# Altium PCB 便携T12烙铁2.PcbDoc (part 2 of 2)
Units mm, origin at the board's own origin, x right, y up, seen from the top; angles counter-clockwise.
Board outline 100 x 95 mm, 2 copper layers (Top Layer, Bottom Layer); 155 components, 22 nets, 605 pads, 185 vias.
Unrouted connection lines stored in the file: 84.
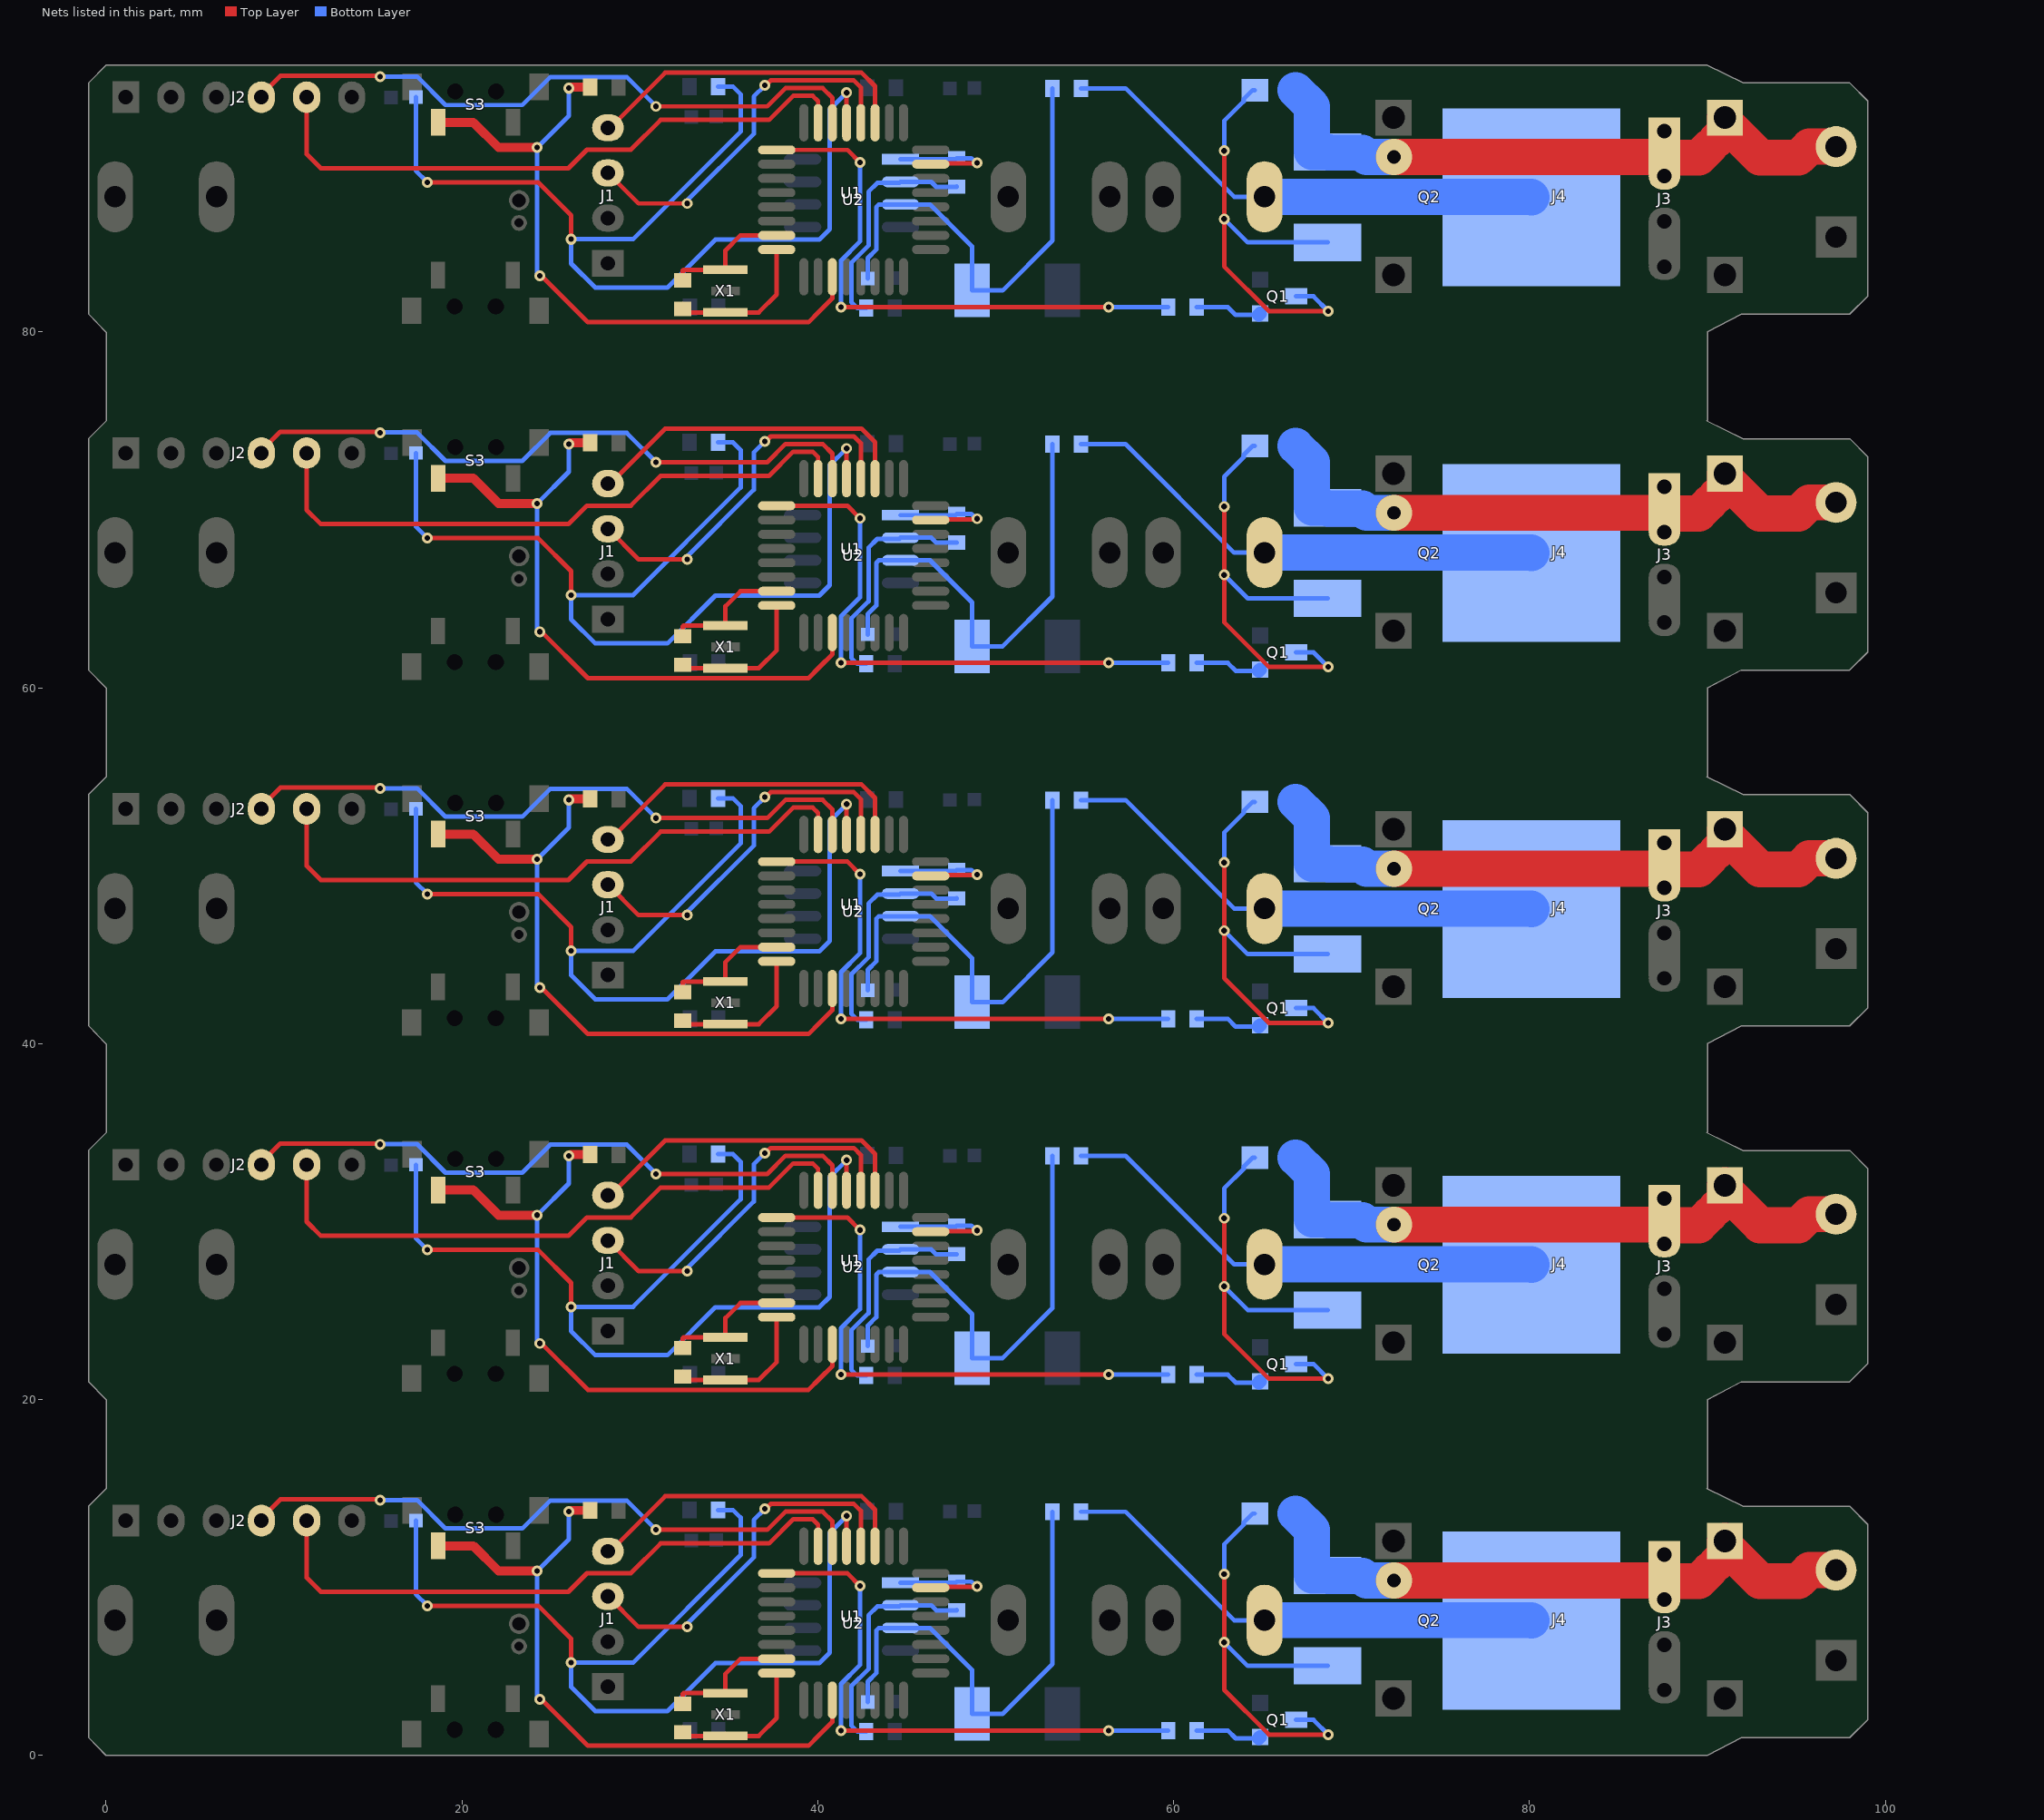
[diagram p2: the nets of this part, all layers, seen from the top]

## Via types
v1: diameter 0.61, hole 0.31, Top Layer to Bottom Layer, 120 vias
v2: diameter 0.62, hole 0.305, Top Layer to Bottom Layer, 30 vias
v3: diameter 0.61, hole 0.33, Top Layer to Bottom Layer, 20 vias
v4: diameter 0.61/0.61 (per signal layer), hole 0.33, Top Layer to Bottom Layer, 10 vias
v5: diameter 2.032/0.61 (per signal layer), hole 0.762, Top Layer to Bottom Layer, 5 vias

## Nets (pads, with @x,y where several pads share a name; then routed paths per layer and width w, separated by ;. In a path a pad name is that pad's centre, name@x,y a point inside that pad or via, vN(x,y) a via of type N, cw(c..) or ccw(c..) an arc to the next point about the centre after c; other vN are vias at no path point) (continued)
NetQ1_B: Q1.B R2.1 | length 18.9
  Bottom Layer w0.254: R2.1@61.297,1.401 63.049,1.401 63.493,0.958 Q1.B@64.785,0.958 ; R2.1@61.297,21.401 63.049,21.401 63.493,20.958 Q1.B@64.785,20.958 ; R2.1@61.297,41.401 63.049,41.401 63.493,40.958 Q1.B@64.785,40.958 ; R2.1@61.297,61.401 63.049,61.401 63.493,60.958 Q1.B@64.785,60.958 ; R2.1@61.297,81.401 63.049,81.401 63.493,80.958 Q1.B@64.785,80.958
  Bottom Layer w0.762: Q1.B@64.785,0.958 Q1.B@64.861,1.034 ; Q1.B@64.785,20.958 Q1.B@64.861,21.034 ; Q1.B@64.785,40.958 Q1.B@64.861,41.034 ; Q1.B@64.785,60.958 Q1.B@64.861,61.034 ; Q1.B@64.785,80.958 Q1.B@64.861,81.034
NetQ1_C: Q1.C Q2.G R3.1 | length 130.5
  Top Layer w0.254: v4(62.846,10.189) v4(62.846,6.354) 62.846,3.687 65.364,1.17 v1(68.696,1.17) ; v4(62.846,30.189) v4(62.846,26.354) 62.846,23.687 65.364,21.17 v1(68.696,21.17) ; v4(62.846,50.189) v4(62.846,46.354) 62.846,43.687 65.364,41.17 v1(68.696,41.17) ; v4(62.846,70.189) v4(62.846,66.354) 62.846,63.687 65.364,61.17 v1(68.696,61.17) ; v4(62.846,90.189) v4(62.846,86.354) 62.846,83.687 65.364,81.17 v1(68.696,81.17)
  Bottom Layer w0.254: v4(62.846,6.354) 64.167,5.033 Q2.G@68.663,5.033 ; v4(62.846,10.189) 62.846,11.866 63.938,12.958 63.938,13.085 64.446,13.593 R3.1@64.573,13.593 ; v4(62.846,26.354) 64.167,25.033 Q2.G@68.663,25.033 ; v4(62.846,30.189) 62.846,31.866 63.938,32.958 63.938,33.085 64.446,33.593 R3.1@64.573,33.593 ; v4(62.846,46.354) 64.167,45.033 Q2.G@68.663,45.033 ; v4(62.846,50.189) 62.846,51.866 63.938,52.958 63.938,53.085 64.446,53.593 R3.1@64.573,53.593 ; v4(62.846,66.354) 64.167,65.033 Q2.G@68.663,65.033 ; v4(62.846,70.189) 62.846,71.866 63.938,72.958 63.938,73.085 64.446,73.593 R3.1@64.573,73.593 ; v4(62.846,86.354) 64.167,85.033 Q2.G@68.663,85.033 ; v4(62.846,90.189) 62.846,91.866 63.938,92.958 63.938,93.085 64.446,93.593 R3.1@64.573,93.593 ; Q1.C@66.893,1.999 67.866,1.999 v1(68.696,1.17) ; Q1.C@66.893,21.999 67.866,21.999 v1(68.696,21.17) ; Q1.C@66.893,41.999 67.866,41.999 v1(68.696,41.17) ; Q1.C@66.893,61.999 67.866,61.999 v1(68.696,61.17) ; Q1.C@66.893,81.999 67.866,81.999 v1(68.696,81.17)
NetR10_1: R10.1 U2.8 X1.3 | length 41.5
  Top Layer w0.254: R10.1@32.415,1.298 32.614,1.1 X1.3@34.816,1.1 36.688,1.1 37.696,2.108 U2.8@37.696,4.631 ; R10.1@32.415,21.298 32.614,21.1 X1.3@34.816,21.1 36.688,21.1 37.696,22.108 U2.8@37.696,24.631 ; R10.1@32.415,41.298 32.614,41.1 X1.3@34.816,41.1 36.688,41.1 37.696,42.108 U2.8@37.696,44.631 ; R10.1@32.415,61.298 32.614,61.1 X1.3@34.816,61.1 36.688,61.1 37.696,62.108 U2.8@37.696,64.631 ; R10.1@32.415,81.298 32.614,81.1 X1.3@34.816,81.1 36.688,81.1 37.696,82.108 U2.8@37.696,84.631
NetR10_2: R10.2 U2.7 X1.1 | length 36.5
  Top Layer w0.254: R10.2@32.415,2.898 32.417,2.9 32.417,3.458 32.456,3.498 X1.1@34.816,3.498 34.816,4.587 35.659,5.431 U2.7@37.696,5.431 ; R10.2@32.415,22.898 32.417,22.9 32.417,23.458 32.456,23.498 X1.1@34.816,23.498 34.816,24.587 35.659,25.431 U2.7@37.696,25.431 ; R10.2@32.415,42.898 32.417,42.9 32.417,43.458 32.456,43.498 X1.1@34.816,43.498 34.816,44.587 35.659,45.431 U2.7@37.696,45.431 ; R10.2@32.415,62.898 32.417,62.9 32.417,63.458 32.456,63.498 X1.1@34.816,63.498 34.816,64.587 35.659,65.431 U2.7@37.696,65.431 ; R10.2@32.415,82.898 32.417,82.9 32.417,83.458 32.456,83.498 X1.1@34.816,83.498 34.816,84.587 35.659,85.431 U2.7@37.696,85.431
PWM_MOS: R2.2 U2.1 | length 159.6
  Top Layer w0.254: U2.1@37.696,10.231 41.672,10.231 v1(42.374,9.529) ; U2.1@37.696,30.231 41.672,30.231 v1(42.374,29.529) ; U2.1@37.696,50.231 41.672,50.231 v1(42.374,49.529) ; U2.1@37.696,70.231 41.672,70.231 v1(42.374,69.529) ; U2.1@37.696,90.231 41.672,90.231 v1(42.374,89.529) ; v1(41.307,1.401) v1(56.344,1.401) ; v1(41.307,21.401) v1(56.344,21.401) ; v1(41.307,41.401) v1(56.344,41.401) ; v1(41.307,61.401) v1(56.344,61.401) ; v1(41.307,81.401) v1(56.344,81.401)
  Bottom Layer w0.254: v1(41.307,1.401) 41.307,4.017 42.374,5.084 v1(42.374,9.529) ; v1(41.307,21.401) 41.307,24.017 42.374,25.084 v1(42.374,29.529) ; v1(41.307,41.401) 41.307,44.017 42.374,45.084 v1(42.374,49.529) ; v1(41.307,61.401) 41.307,64.017 42.374,65.084 v1(42.374,69.529) ; v1(41.307,81.401) 41.307,84.017 42.374,85.084 v1(42.374,89.529) ; v1(56.344,1.401) R2.2@59.697,1.401 ; v1(56.344,21.401) R2.2@59.697,21.401 ; v1(56.344,41.401) R2.2@59.697,41.401 ; v1(56.344,61.401) R2.2@59.697,61.401 ; v1(56.344,81.401) R2.2@59.697,81.401
R_but: R8.2 S3.2 U2.11 | length 190
  Top Layer w0.254: v1(24.391,3.154) 24.477,3.154 27.085,0.546 39.482,0.546 40.112,1.176 40.823,1.887 U2.11@40.823,3.104 ; v1(24.391,23.154) 24.477,23.154 27.085,20.546 39.482,20.546 40.112,21.176 40.823,21.887 U2.11@40.823,23.104 ; v1(24.391,43.154) 24.477,43.154 27.085,40.546 39.482,40.546 40.112,41.176 40.823,41.887 U2.11@40.823,43.104 ; v1(24.391,63.154) 24.477,63.154 27.085,60.546 39.482,60.546 40.112,61.176 40.823,61.887 U2.11@40.823,63.104 ; v1(24.391,83.154) 24.477,83.154 27.085,80.546 39.482,80.546 40.112,81.176 40.823,81.887 U2.11@40.823,83.104
  Top Layer w0.508: S3.2@18.674,11.779 20.643,11.779 22.054,10.367 v1(24.238,10.367) ; S3.2@18.674,31.779 20.643,31.779 22.054,30.367 v1(24.238,30.367) ; S3.2@18.674,51.779 20.643,51.779 22.054,50.367 v1(24.238,50.367) ; S3.2@18.674,71.779 20.643,71.779 22.054,70.367 v1(24.238,70.367) ; S3.2@18.674,91.779 20.643,91.779 22.054,90.367 v1(24.238,90.367) ; v2(26.016,13.699) 26.046,13.699 26.118,13.771 R8.2@27.21,13.771 ; v2(26.016,33.699) 26.046,33.699 26.118,33.771 R8.2@27.21,33.771 ; v2(26.016,53.699) 26.046,53.699 26.118,53.771 R8.2@27.21,53.771 ; v2(26.016,73.699) 26.046,73.699 26.118,73.771 R8.2@27.21,73.771 ; v2(26.016,93.699) 26.046,93.699 26.118,93.771 R8.2@27.21,93.771
  Bottom Layer w0.254: v1(24.391,3.154) 24.238,3.306 v1(24.238,10.367) 26.016,12.145 v2(26.016,13.699) ; v1(24.391,23.154) 24.238,23.306 v1(24.238,30.367) 26.016,32.145 v2(26.016,33.699) ; v1(24.391,43.154) 24.238,43.306 v1(24.238,50.367) 26.016,52.145 v2(26.016,53.699) ; v1(24.391,63.154) 24.238,63.306 v1(24.238,70.367) 26.016,72.145 v2(26.016,73.699) ; v1(24.391,83.154) 24.238,83.306 v1(24.238,90.367) 26.016,92.145 v2(26.016,93.699)
Reset: C2.2 R9.1 U2.29 | length 292.4
  Top Layer w0.254: v2(18.066,8.411) 24.289,8.411 26.143,6.557 v2(26.143,5.211) ; v2(18.066,28.411) 24.289,28.411 26.143,26.557 v2(26.143,25.211) ; v2(18.066,48.411) 24.289,48.411 26.143,46.557 v2(26.143,45.211) ; v2(18.066,68.411) 24.289,68.411 26.143,66.557 v2(26.143,65.211) ; v2(18.066,88.411) 24.289,88.411 26.143,86.557 v2(26.143,85.211) ; U2.29@41.576,11.805 U2.29@41.623,11.758 v3(41.623,13.455) ; U2.29@41.576,31.805 U2.29@41.623,31.758 v3(41.623,33.455) ; U2.29@41.576,51.805 U2.29@41.623,51.758 v3(41.623,53.455) ; U2.29@41.576,71.805 U2.29@41.623,71.758 v3(41.623,73.455) ; U2.29@41.576,91.805 U2.29@41.623,91.758 v3(41.623,93.455)
  Bottom Layer w0.254: C2.2@17.414,13.199 17.414,9.063 v2(18.066,8.411) ; C2.2@17.414,33.199 17.414,29.063 v2(18.066,28.411) ; C2.2@17.414,53.199 17.414,49.063 v2(18.066,48.411) ; C2.2@17.414,73.199 17.414,69.063 v2(18.066,68.411) ; C2.2@17.414,93.199 17.414,89.063 v2(18.066,88.411) ; R9.1@34.398,13.796 35.236,13.796 35.668,13.365 35.668,11.256 29.623,5.211 v2(26.143,5.211) 26.143,3.847 27.497,2.493 31.553,2.493 34.246,5.186 40.088,5.186 40.672,5.77 40.672,12.505 v3(41.623,13.455) ; R9.1@34.398,33.796 35.236,33.796 35.668,33.365 35.668,31.256 29.623,25.211 v2(26.143,25.211) 26.143,23.847 27.497,22.493 31.553,22.493 34.246,25.186 40.088,25.186 40.672,25.77 40.672,32.505 v3(41.623,33.455) ; R9.1@34.398,53.796 35.236,53.796 35.668,53.365 35.668,51.256 29.623,45.211 v2(26.143,45.211) 26.143,43.847 27.497,42.493 31.553,42.493 34.246,45.186 40.088,45.186 40.672,45.77 40.672,52.505 v3(41.623,53.455) ; R9.1@34.398,73.796 35.236,73.796 35.668,73.365 35.668,71.256 29.623,65.211 v2(26.143,65.211) 26.143,63.847 27.497,62.493 31.553,62.493 34.246,65.186 40.088,65.186 40.672,65.77 40.672,72.505 v3(41.623,73.455) ; R9.1@34.398,93.796 35.236,93.796 35.668,93.364 35.668,91.256 29.623,85.211 v2(26.143,85.211) 26.143,83.847 27.497,82.493 31.553,82.493 34.246,85.186 40.088,85.186 40.672,85.77 40.672,92.505 v3(41.623,93.455)
RX: J2.4 U2.30 | length 183.7
  Top Layer w0.254: J2.4@8.735,13.198 8.735,13.325 9.802,14.392 15.369,14.392 v1(15.416,14.345) ; J2.4@8.735,33.198 8.735,33.325 9.802,34.392 15.369,34.392 v1(15.416,34.345) ; J2.4@8.735,53.198 8.735,53.325 9.802,54.392 15.369,54.392 v1(15.416,54.345) ; J2.4@8.735,73.198 8.735,73.325 9.802,74.392 15.369,74.392 v1(15.416,74.345) ; J2.4@8.735,93.198 8.735,93.325 9.802,94.392 15.369,94.392 v1(15.416,94.345) ; v1(30.918,12.679) 37.167,12.679 38.191,13.703 40.282,13.703 40.823,13.163 U2.30@40.823,11.758 ; v1(30.918,32.679) 37.167,32.679 38.191,33.703 40.282,33.703 40.823,33.163 U2.30@40.823,31.758 ; v1(30.918,52.679) 37.167,52.679 38.191,53.703 40.282,53.703 40.823,53.163 U2.30@40.823,51.758 ; v1(30.918,72.679) 37.167,72.679 38.191,73.703 40.282,73.703 40.823,73.163 U2.30@40.823,71.758 ; v1(30.918,92.679) 37.167,92.679 38.191,93.703 40.282,93.703 40.823,93.163 U2.30@40.823,91.758
  Bottom Layer w0.254: v1(15.416,14.345) 15.426,14.355 17.482,14.355 19.082,12.755 23.4,12.755 24.975,14.33 29.267,14.33 v1(30.918,12.679) ; v1(15.416,34.345) 15.426,34.355 17.482,34.355 19.082,32.755 23.4,32.755 24.975,34.33 29.267,34.33 v1(30.918,32.679) ; v1(15.416,54.345) 15.426,54.355 17.482,54.355 19.082,52.755 23.4,52.755 24.975,54.33 29.267,54.33 v1(30.918,52.679) ; v1(15.416,74.345) 15.426,74.355 17.482,74.355 19.082,72.755 23.4,72.755 24.975,74.33 29.267,74.33 v1(30.918,72.679) ; v1(15.416,94.345) 15.426,94.355 17.482,94.355 19.082,92.755 23.4,92.755 24.975,94.33 29.267,94.33 v1(30.918,92.679)
SCL: J1.3 U2.28 | length 106.3
  Top Layer w0.254: J1.3@28.214,8.938 29.93,7.222 v1(32.671,7.222) ; J1.3@28.214,28.938 29.93,27.222 v1(32.671,27.222) ; J1.3@28.214,48.938 29.93,47.222 v1(32.671,47.222) ; J1.3@28.214,68.938 29.93,67.222 v1(32.671,67.222) ; J1.3@28.214,88.938 29.93,87.222 v1(32.671,87.222) ; v1(37.032,13.86) 37.083,13.86 37.359,14.135 42.035,14.135 42.423,13.747 U2.28@42.423,11.758 ; v1(37.032,33.86) 37.083,33.86 37.359,34.135 42.035,34.135 42.423,33.747 U2.28@42.423,31.758 ; v1(37.032,53.86) 37.083,53.86 37.359,54.135 42.035,54.135 42.423,53.747 U2.28@42.423,51.758 ; v1(37.032,73.86) 37.083,73.86 37.359,74.135 42.035,74.135 42.423,73.747 U2.28@42.423,71.758 ; v1(37.032,93.86) 37.083,93.86 37.359,94.135 42.035,94.135 42.423,93.747 U2.28@42.423,91.758
  Bottom Layer w0.254: v1(32.671,7.222) 32.671,7.394 36.405,11.128 36.405,13.232 v1(37.032,13.86) ; v1(32.671,27.222) 32.671,27.394 36.405,31.128 36.405,33.232 v1(37.032,33.86) ; v1(32.671,47.222) 32.671,47.394 36.405,51.128 36.405,53.232 v1(37.032,53.86) ; v1(32.671,67.222) 32.671,67.394 36.405,71.128 36.405,73.232 v1(37.032,73.86) ; v1(32.671,87.222) 32.671,87.394 36.405,91.128 36.405,93.232 v1(37.032,93.86)
SDA: J1.4 U2.27 | length 93.3
  Top Layer w0.254: J1.4@28.214,11.478 28.341,11.478 31.43,14.567 42.467,14.567 43.223,13.811 U2.27@43.223,11.758 ; J1.4@28.214,31.478 28.341,31.478 31.43,34.567 42.467,34.567 43.223,33.811 U2.27@43.223,31.758 ; J1.4@28.214,51.478 28.341,51.478 31.43,54.567 42.467,54.567 43.223,53.811 U2.27@43.223,51.758 ; J1.4@28.214,71.478 28.341,71.478 31.43,74.567 42.467,74.567 43.223,73.811 U2.27@43.223,71.758 ; J1.4@28.214,91.478 28.341,91.478 31.43,94.567 42.467,94.567 43.223,93.811 U2.27@43.223,91.758
TEMP: R5.1 U1.1 U2.23 | length 35.3
  Top Layer w0.254: U2.23@46.35,9.431 46.386,9.467 48.916,9.467 v1(48.952,9.503) ; U2.23@46.35,29.431 46.386,29.467 48.916,29.467 v1(48.952,29.503) ; U2.23@46.35,49.431 46.386,49.467 48.916,49.467 v1(48.952,49.503) ; U2.23@46.35,69.431 46.386,69.467 48.916,69.467 v1(48.952,69.503) ; U2.23@46.35,89.431 46.386,89.467 48.916,89.467 v1(48.952,89.503)
  Bottom Layer w0.254: U1.1@44.655,9.707 47.755,9.707 R5.1@47.817,9.769 48.639,9.769 48.904,9.503 v1(48.952,9.503) ; U1.1@44.655,29.707 47.755,29.707 R5.1@47.817,29.769 48.639,29.769 48.904,29.503 v1(48.952,29.503) ; U1.1@44.655,49.707 47.755,49.707 R5.1@47.817,49.769 48.639,49.769 48.904,49.503 v1(48.952,49.503) ; U1.1@44.655,69.707 47.755,69.707 R5.1@47.817,69.769 48.639,69.769 48.904,69.503 v1(48.952,69.503) ; U1.1@44.655,89.707 47.755,89.707 R5.1@47.817,89.769 48.639,89.769 48.904,89.503 v1(48.952,89.503)
TEMP_sense: P2.1 Q2.D R1.1 | length 139.3
  Bottom Layer w0.254: R1.1@54.794,13.695 57.307,13.695 63.403,7.599 P2.1@65.114,7.599 ; R1.1@54.794,33.695 57.307,33.695 63.403,27.599 P2.1@65.114,27.599 ; R1.1@54.794,53.695 57.307,53.695 63.403,47.599 P2.1@65.114,47.599 ; R1.1@54.794,73.695 57.307,73.695 63.403,67.599 P2.1@65.114,67.599 ; R1.1@54.794,93.695 57.307,93.695 63.403,87.599 P2.1@65.114,87.599
  Bottom Layer w2.032: P2.1@65.114,7.599 80.087,7.599 Q2.D@80.113,7.573 ; P2.1@65.114,27.599 80.087,27.599 Q2.D@80.113,27.573 ; P2.1@65.114,47.599 80.087,47.599 Q2.D@80.113,47.573 ; P2.1@65.114,67.599 80.087,67.599 Q2.D@80.113,67.573 ; P2.1@65.114,87.599 80.087,87.599 Q2.D@80.113,87.573
TX: J2.5 U2.31 | length 176.5
  Top Layer w0.254: J2.5@11.275,13.198 11.275,9.995 12.072,9.199 25.991,9.199 27.032,10.24 29.496,10.24 31.172,11.917 37.268,11.917 38.623,13.271 39.724,13.271 40.023,12.972 U2.31@40.023,11.758 ; J2.5@11.275,33.198 11.275,29.995 12.072,29.199 25.991,29.199 27.032,30.24 29.496,30.24 31.172,31.917 37.268,31.917 38.623,33.272 39.724,33.272 40.023,32.972 U2.31@40.023,31.758 ; J2.5@11.275,53.198 11.275,49.995 12.072,49.199 25.991,49.199 27.032,50.24 29.496,50.24 31.172,51.917 37.268,51.917 38.623,53.271 39.724,53.271 40.023,52.972 U2.31@40.023,51.758 ; J2.5@11.275,73.198 11.275,69.995 12.072,69.199 25.991,69.199 27.032,70.24 29.496,70.24 31.172,71.917 37.268,71.917 38.623,73.272 39.724,73.272 40.023,72.972 U2.31@40.023,71.758 ; J2.5@11.275,93.198 11.275,89.995 12.072,89.199 25.991,89.199 27.032,90.24 29.496,90.24 31.172,91.917 37.268,91.917 38.623,93.271 39.724,93.271 40.023,92.972 U2.31@40.023,91.758
V+: C1.2 R1.2 SS1.K U1.3 | length 136.8
  Bottom Layer w0.254: C1.2@42.813,3.001 42.813,4.15 43.288,4.625 43.288,7.018 43.437,7.167 U1.3@44.655,7.167 46.311,7.167 48.677,4.801 SS1.K@48.677,2.333 50.392,2.333 53.194,5.135 R1.2@53.194,13.695 ; C1.2@42.813,23.001 42.813,24.15 43.288,24.625 43.288,27.018 43.437,27.167 U1.3@44.655,27.167 46.311,27.167 48.677,24.801 SS1.K@48.677,22.333 50.392,22.333 53.194,25.135 R1.2@53.194,33.695 ; C1.2@42.813,43.001 42.813,44.15 43.288,44.625 43.288,47.018 43.437,47.167 U1.3@44.655,47.167 46.311,47.167 48.677,44.801 SS1.K@48.677,42.333 50.392,42.333 53.194,45.135 R1.2@53.194,53.695 ; C1.2@42.813,63.001 42.813,64.15 43.288,64.625 43.288,67.018 43.437,67.167 U1.3@44.655,67.167 46.311,67.167 48.677,64.801 SS1.K@48.677,62.333 50.392,62.333 53.194,65.135 R1.2@53.194,73.695 ; C1.2@42.813,83.001 42.813,84.15 43.288,84.625 43.288,87.018 43.437,87.167 U1.3@44.655,87.167 46.311,87.167 48.677,84.801 SS1.K@48.677,82.333 50.392,82.333 53.194,85.135 R1.2@53.194,93.695
V-: R4.1 R5.2 U1.2 | length 64.4
  Bottom Layer w0.254: R4.1@42.73,1.35 42.221,1.35 41.891,1.68 41.891,3.89 42.856,4.855 42.856,7.878 43.349,8.371 44.589,8.371 U1.2@44.655,8.437 46.387,8.437 46.666,8.157 47.806,8.157 R5.2@47.817,8.169 ; R4.1@42.73,21.35 42.221,21.35 41.891,21.68 41.891,23.89 42.856,24.855 42.856,27.878 43.349,28.371 44.589,28.371 U1.2@44.655,28.437 46.387,28.437 46.666,28.157 47.806,28.157 R5.2@47.817,28.169 ; R4.1@42.73,41.35 42.221,41.35 41.891,41.68 41.891,43.89 42.856,44.855 42.856,47.878 43.349,48.371 44.589,48.371 U1.2@44.655,48.437 46.387,48.437 46.666,48.157 47.806,48.157 R5.2@47.817,48.169 ; R4.1@42.73,61.35 42.221,61.35 41.891,61.68 41.891,63.89 42.856,64.855 42.856,67.878 43.349,68.371 44.589,68.371 U1.2@44.655,68.437 46.387,68.437 46.666,68.157 47.806,68.157 R5.2@47.817,68.169 ; R4.1@42.73,81.35 42.221,81.35 41.891,81.68 41.891,83.89 42.856,84.855 42.856,87.878 43.349,88.371 44.589,88.371 U1.2@44.655,88.437 46.387,88.437 46.666,88.157 47.806,88.157 R5.2@47.817,88.169
VCC: J3.1 J4.IN+ J5.2 Q2.S R3.2 | length 176.8
  Top Layer w2.032: v5(72.397,9.834) 87.554,9.834 J3.1@87.59,9.798 89.52,9.798 90.133,10.411 ; v5(72.397,29.834) 87.554,29.834 J3.1@87.59,29.798 89.52,29.798 90.133,30.411 ; v5(72.397,49.834) 87.554,49.834 J3.1@87.59,49.798 89.52,49.798 90.133,50.411 ; v5(72.397,69.834) 87.554,69.834 J3.1@87.59,69.798 89.52,69.798 90.133,70.411 ; v5(72.397,89.834) 87.554,89.834 J3.1@87.59,89.798 89.52,89.798 90.133,90.411 ; 90.514,10.792 90.989,11.268 J4.IN+@90.989,11.779 ; 90.514,30.792 90.989,31.268 J4.IN+@90.989,31.779 ; 90.514,50.792 90.989,51.268 J4.IN+@90.989,51.779 ; 90.514,70.792 90.989,71.268 J4.IN+@90.989,71.779 ; 90.514,90.792 90.989,91.268 J4.IN+@90.989,91.779 ; J4.IN+@90.989,12.044 J4.IN+@90.989,11.779 ; J4.IN+@90.989,32.044 J4.IN+@90.989,31.779 ; J4.IN+@90.989,52.044 J4.IN+@90.989,51.779 ; J4.IN+@90.989,72.044 J4.IN+@90.989,71.779 ; J4.IN+@90.989,92.044 J4.IN+@90.989,91.779 ; J5.2@97.238,10.418 95.739,10.418 95.119,9.798 92.971,9.798 J4.IN+@90.989,11.779 ; J5.2@97.238,30.418 95.739,30.418 95.119,29.798 92.971,29.798 J4.IN+@90.989,31.779 ; J5.2@97.238,50.418 95.739,50.418 95.119,49.798 92.971,49.798 J4.IN+@90.989,51.779 ; J5.2@97.238,70.418 95.739,70.418 95.119,69.798 92.971,69.798 J4.IN+@90.989,71.779 ; J5.2@97.238,90.418 95.739,90.418 95.119,89.798 92.971,89.798 J4.IN+@90.989,91.779
  Bottom Layer w2.032: R3.2@66.859,13.593 67.779,12.674 67.779,10.147 67.813,10.113 Q2.S@68.663,10.113 68.697,10.079 70.615,10.079 70.861,9.834 v5(72.397,9.834) ; R3.2@66.859,33.593 67.779,32.674 67.779,30.147 67.813,30.113 Q2.S@68.663,30.113 68.697,30.079 70.615,30.079 70.861,29.834 v5(72.397,29.834) ; R3.2@66.859,53.593 67.779,52.674 67.779,50.147 67.813,50.113 Q2.S@68.663,50.113 68.697,50.079 70.615,50.079 70.861,49.834 v5(72.397,49.834) ; R3.2@66.859,73.593 67.779,72.674 67.779,70.147 67.813,70.113 Q2.S@68.663,70.113 68.697,70.079 70.615,70.079 70.861,69.834 v5(72.397,69.834) ; R3.2@66.859,93.593 67.779,92.674 67.779,90.147 67.813,90.113 Q2.S@68.663,90.113 68.697,90.079 70.615,90.079 70.861,89.834 v5(72.397,89.834)
pads on no net: J2.2 P1.1 P1.2 P2.2 P3.2 S2.0 S3.0 U1.5 U1.6 U1.7 U2.9 U2.10 U2.12 U2.13 U2.14 U2.15 U2.16 U2.17 U2.19 U2.22 U2.25 U2.26 U2.32

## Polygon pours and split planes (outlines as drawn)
GND on Bottom Layer "GND_L02_P000" (solid, remove dead copper, pour order 0): -8.763,101.727 -4.953,97.917 103.124,97.917 103.124,0.254 98.933,-3.937 98.298,-3.302 -6.223,-3.302
GND on Top Layer "GND_L01_P001" (solid, remove dead copper, pour order 1): -12.7,106.299 106.299,106.299 109.601,102.997 104.648,98.044 104.648,-10.922 -2.921,-10.922 -12.446,-1.397

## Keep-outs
Keep-Out Layer:
  lines w0.254: 0,20 -0.986,21.008 -0.986,33.998 0.015,34.999 0.015,39.985 ; 0,40 -0.986,41.008 -0.986,53.998 0.015,54.999 0.015,59.985 ; 0,60 -0.986,61.008 -0.986,73.998 0.015,74.999 0.015,79.985 ; 0,80 -0.986,81.008 -0.986,93.998 0.015,94.999 89.98,94.999 92.014,93.998 98.008,93.998 99.014,92.984 99.014,82.012 98.003,80.998 91.915,80.998 90.013,80 90.013,75.032 ; 0.015,19.985 0.015,14.999 -0.986,13.998 -0.986,1.008 0,0 90.013,0 91.915,0.998 98.003,0.998 99.014,2.012 99.014,12.984 98.008,13.998 92.014,13.998 89.98,14.999 ; 5,14.999 5,19.999 54.75,19.999 ; 5,34.999 5,39.999 54.75,39.999 ; 5,54.999 5,59.999 54.75,59.999 ; 5,74.999 5,79.999 54.75,79.999 ; 5.015,14.999 54.765,14.999 54.765,19.999 ; 5.015,34.999 54.765,34.999 54.765,39.999 ; 5.015,54.999 54.765,54.999 54.765,59.999 ; 5.015,74.999 54.765,74.999 54.765,79.999 ; 89.98,34.999 92.014,33.998 98.008,33.998 99.014,32.984 99.014,22.012 98.003,20.998 91.915,20.998 90.013,20 90.013,15.032 ; 89.98,54.999 92.014,53.998 98.008,53.998 99.014,52.984 99.014,42.012 98.003,40.998 91.915,40.998 90.013,40 90.013,35.032 ; 89.98,74.999 92.014,73.998 98.008,73.998 99.014,72.984 99.014,62.012 98.003,60.998 91.915,60.998 90.013,60 90.013,55.032 ; 59.765,14.999 84.979,14.999 84.979,19.999 59.765,19.999 59.765,14.999 ; 59.765,34.999 59.765,39.999 84.979,39.999 84.979,34.999 59.765,34.999 ; 59.765,54.999 59.765,59.999 84.979,59.999 84.979,54.999 59.765,54.999 ; 59.765,74.999 59.765,79.999 84.979,79.999 84.979,74.999 59.765,74.999

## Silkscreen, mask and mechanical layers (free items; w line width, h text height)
Top Overlay:
  text "2K" at 29.775,93.212 h1.27
  text "24V" at 93.479,91.383 h2.54
  text "5V" at 67.85,91.231 h2.54
  text "GND" at 0.032,90.935 h1.27
  text "5V" at 5.569,90.94 h1.27
  text "RX" at 8.16,90.932 h1.27
  text "TX" at 10.649,90.932 h1.27
  text "DTR" at 12.808,90.932 h1.27
  text "SDA" at 29.748,90.819 h1.27
  text "SCL" at 29.648,88.149 h1.27
  text "T-" at 52.762,86.887 h2.54
  text "T+" at 60.992,86.735 h2.54
  text "5V" at 29.721,86.011 h1.27
  text "Vibrate" at 8.367,85.371 h1.27
  text "16M" at 33.357,84.982 h1.27
  text "GND" at 29.62,83.623 h1.27
  text "I2C" at 26.603,82.59 h1.27 r90
  text "GND" at 93.377,82.315 h2.54
  text "GND" at 65.589,82.29 h2.54
  text "1M" at 29.064,81.223 h1.27
  text "2K" at 29.775,73.212 h1.27
  text "24V" at 93.479,71.383 h2.54
  text "5V" at 67.85,71.231 h2.54
  text "GND" at 0.032,70.935 h1.27
  text "5V" at 5.569,70.94 h1.27
  text "RX" at 8.16,70.932 h1.27
  text "TX" at 10.649,70.932 h1.27
  text "DTR" at 12.808,70.932 h1.27
  text "SDA" at 29.748,70.819 h1.27
  text "SCL" at 29.648,68.149 h1.27
  text "T-" at 52.762,66.887 h2.54
  text "T+" at 60.992,66.735 h2.54
  text "5V" at 29.721,66.011 h1.27
  text "Vibrate" at 8.367,65.371 h1.27
  text "16M" at 33.357,64.982 h1.27
  text "GND" at 29.62,63.623 h1.27
  text "I2C" at 26.603,62.59 h1.27 r90
  text "GND" at 93.377,62.315 h2.54
  text "GND" at 65.589,62.29 h2.54
  text "1M" at 29.064,61.223 h1.27
  text "2K" at 29.775,53.212 h1.27
  text "24V" at 93.479,51.383 h2.54
  text "5V" at 67.85,51.231 h2.54
  text "5V" at 5.569,50.94 h1.27
  text "GND" at 0.032,50.935 h1.27
  text "RX" at 8.16,50.932 h1.27
  text "TX" at 10.649,50.932 h1.27
  text "DTR" at 12.808,50.932 h1.27
  text "SDA" at 29.748,50.819 h1.27
  text "SCL" at 29.648,48.149 h1.27
  text "T-" at 52.762,46.887 h2.54
  text "T+" at 60.992,46.735 h2.54
  text "5V" at 29.721,46.011 h1.27
  text "Vibrate" at 8.367,45.371 h1.27
  text "16M" at 33.357,44.982 h1.27
  text "GND" at 29.62,43.623 h1.27
  text "I2C" at 26.603,42.59 h1.27 r90
  text "GND" at 93.377,42.315 h2.54
  text "GND" at 65.589,42.29 h2.54
  text "1M" at 29.064,41.223 h1.27
  text "2K" at 29.775,33.212 h1.27
  text "24V" at 93.479,31.383 h2.54
  text "5V" at 67.85,31.231 h2.54
  text "GND" at 0.032,30.935 h1.27
  text "5V" at 5.569,30.94 h1.27
  text "RX" at 8.16,30.932 h1.27
  text "TX" at 10.649,30.932 h1.27
  text "DTR" at 12.808,30.932 h1.27
  text "SDA" at 29.748,30.819 h1.27
  text "SCL" at 29.648,28.149 h1.27
  text "T-" at 52.762,26.887 h2.54
  text "T+" at 60.992,26.735 h2.54
  text "5V" at 29.721,26.011 h1.27
  text "Vibrate" at 8.367,25.371 h1.27
  text "16M" at 33.357,24.982 h1.27
  text "GND" at 29.62,23.623 h1.27
  text "I2C" at 26.603,22.59 h1.27 r90
  text "GND" at 93.377,22.315 h2.54
  text "GND" at 65.589,22.29 h2.54
  text "1M" at 29.064,21.223 h1.27
  text "2K" at 29.775,13.212 h1.27
  text "24V" at 93.479,11.383 h2.54
  text "5V" at 67.85,11.231 h2.54
  text "GND" at 0.032,10.935 h1.27
  text "5V" at 5.569,10.94 h1.27
  text "RX" at 8.16,10.932 h1.27
  text "TX" at 10.649,10.932 h1.27
  text "DTR" at 12.808,10.932 h1.27
  text "SDA" at 29.748,10.819 h1.27
  text "SCL" at 29.648,8.149 h1.27
  text "T-" at 52.762,6.887 h2.54
  text "T+" at 60.992,6.735 h2.54
  text "5V" at 29.721,6.011 h1.27
  text "Vibrate" at 8.367,5.371 h1.27
  text "16M" at 33.357,4.982 h1.27
  text "GND" at 29.62,3.623 h1.27
  text "I2C" at 26.603,2.59 h1.27 r90
  text "GND" at 93.377,2.315 h2.54
  text "GND" at 65.589,2.29 h2.54
  text "1M" at 29.064,1.223 h1.27
Bottom Overlay:
  lines w0.25: 9.114,7.6 37.015,7.6 ; 9.114,27.6 37.015,27.6 ; 9.114,47.6 37.015,47.6 ; 9.114,67.6 37.015,67.6 ; 9.114,87.6 37.015,87.6 ; 9.314,6.8 8.514,7.6 9.314,8.4 ; 9.314,26.8 8.514,27.6 9.314,28.4 ; 9.314,46.8 8.514,47.6 9.314,48.4 ; 9.314,66.8 8.514,67.6 9.314,68.4 ; 9.314,86.8 8.514,87.6 9.314,88.4
  text "10K" at 40.774,93.771 h1.27
  text "10K" at 62.922,93.466 h1.27
  text "10K" at 31.782,93.11 h1.27
  text "0.1u" at 50.426,91.84 h1.27
  text "5V" at 6.774,91.637 h1.27 r90
  text "RX" at 9.379,91.637 h1.27 r90
  text "TX" at 11.767,91.637 h1.27 r90
  text "DTR" at 14.358,91.637 h1.27 r90
  text "10K" at 55.607,91.434 h1.27
  text "LM358G" at 44.05,91.282 h1.27
  text "GND" at 2.618,90.918 h1.27
  text "200K" at 50.527,90.748 h1.27
  text "0.1u" at 17.863,90.469 h1.27
  text "TypeC快充" at 91.828,90.393 h1.27 r90
  text "0.1u" at 33.611,89.554 h1.27
  text "T-" at 54.642,86.862 h2.54
  text "T+" at 63.659,86.735 h2.54
  text "T12" at 12.417,85.926 h1.14
  text "SS12" at 48.978,84.373 h1.27
  text "2.2n" at 41.739,83.052 h1.27
  text "2SC3356" at 63.786,82.747 h1.27
  text "1K" at 58.655,81.63 h1.27
  text "2K" at 31.833,81.274 h1.27
  text "1K" at 40.748,81.122 h1.27
  text "10K" at 40.774,73.771 h1.27
  text "10K" at 62.922,73.466 h1.27
  text "10K" at 31.782,73.11 h1.27
  text "0.1u" at 50.426,71.84 h1.27
  text "5V" at 6.774,71.637 h1.27 r90
  text "RX" at 9.379,71.637 h1.27 r90
  text "TX" at 11.767,71.637 h1.27 r90
  text "DTR" at 14.358,71.637 h1.27 r90
  text "10K" at 55.607,71.434 h1.27
  text "LM358G" at 44.05,71.282 h1.27
  text "GND" at 2.618,70.918 h1.27
  text "200K" at 50.527,70.748 h1.27
  text "0.1u" at 17.863,70.469 h1.27
  text "TypeC快充" at 91.828,70.393 h1.27 r90
  text "0.1u" at 33.611,69.554 h1.27
  text "T-" at 54.642,66.862 h2.54
  text "T+" at 63.659,66.735 h2.54
  text "T12" at 12.417,65.926 h1.14
  text "SS12" at 48.978,64.373 h1.27
  text "2.2n" at 41.739,63.052 h1.27
  text "2SC3356" at 63.786,62.747 h1.27
  text "1K" at 58.655,61.63 h1.27
  text "2K" at 31.833,61.274 h1.27
  text "1K" at 40.748,61.122 h1.27
  text "10K" at 40.774,53.771 h1.27
  text "10K" at 62.922,53.466 h1.27
  text "10K" at 31.782,53.11 h1.27
  text "0.1u" at 50.426,51.84 h1.27
  text "5V" at 6.774,51.637 h1.27 r90
  text "RX" at 9.379,51.637 h1.27 r90
  text "TX" at 11.767,51.637 h1.27 r90
  text "DTR" at 14.358,51.637 h1.27 r90
  text "10K" at 55.607,51.434 h1.27
  text "LM358G" at 44.05,51.282 h1.27
  text "GND" at 2.618,50.918 h1.27
  text "200K" at 50.527,50.748 h1.27
  text "0.1u" at 17.863,50.469 h1.27
  text "TypeC快充" at 91.828,50.393 h1.27 r90
  text "0.1u" at 33.611,49.554 h1.27
  text "T-" at 54.642,46.862 h2.54
  text "T+" at 63.659,46.735 h2.54
  text "T12" at 12.417,45.926 h1.14
  text "SS12" at 48.978,44.373 h1.27
  text "2.2n" at 41.739,43.052 h1.27
  text "2SC3356" at 63.786,42.747 h1.27
  text "1K" at 58.655,41.63 h1.27
  text "2K" at 31.833,41.274 h1.27
  text "1K" at 40.748,41.122 h1.27
  text "10K" at 40.774,33.771 h1.27
  text "10K" at 62.922,33.466 h1.27
  text "10K" at 31.782,33.11 h1.27
  text "0.1u" at 50.426,31.84 h1.27
  text "5V" at 6.774,31.637 h1.27 r90
  text "RX" at 9.379,31.637 h1.27 r90
  text "TX" at 11.767,31.637 h1.27 r90
  text "DTR" at 14.358,31.637 h1.27 r90
  text "10K" at 55.607,31.434 h1.27
  text "LM358G" at 44.05,31.282 h1.27
  text "GND" at 2.618,30.918 h1.27
  text "200K" at 50.527,30.748 h1.27
  text "0.1u" at 17.863,30.469 h1.27
  text "TypeC快充" at 91.828,30.393 h1.27 r90
  text "0.1u" at 33.611,29.554 h1.27
  text "T-" at 54.642,26.862 h2.54
  text "T+" at 63.659,26.735 h2.54
  text "T12" at 12.417,25.926 h1.14
  text "SS12" at 48.978,24.373 h1.27
  text "2.2n" at 41.739,23.052 h1.27
  text "2SC3356" at 63.786,22.747 h1.27
  text "1K" at 58.655,21.63 h1.27
  text "2K" at 31.833,21.274 h1.27
  text "1K" at 40.748,21.122 h1.27
  text "10K" at 40.774,13.771 h1.27
  text "10K" at 62.922,13.466 h1.27
  text "10K" at 31.782,13.11 h1.27
  text "0.1u" at 50.426,11.84 h1.27
  text "5V" at 6.774,11.637 h1.27 r90
  text "RX" at 9.379,11.637 h1.27 r90
  text "TX" at 11.767,11.637 h1.27 r90
  text "DTR" at 14.358,11.637 h1.27 r90
  text "10K" at 55.607,11.434 h1.27
  text "LM358G" at 44.05,11.282 h1.27
  text "GND" at 2.618,10.918 h1.27
  text "200K" at 50.527,10.748 h1.27
  text "0.1u" at 17.863,10.469 h1.27
  text "TypeC快充" at 91.828,10.393 h1.27 r90
  text "0.1u" at 33.611,9.554 h1.27
  text "T-" at 54.642,6.862 h2.54
  text "T+" at 63.659,6.735 h2.54
  text "T12" at 12.417,5.926 h1.14
  text "SS12" at 48.978,4.373 h1.27
  text "2.2n" at 41.739,3.052 h1.27
  text "2SC3356" at 63.786,2.747 h1.27
  text "1K" at 58.655,1.63 h1.27
  text "2K" at 31.833,1.274 h1.27
  text "1K" at 40.748,1.122 h1.27
Mechanical 1:
  lines w0.254: 0,35.014 0,40 0,40.023 -0.986,41.008 -0.986,53.998 0.015,54.999 ; 0,55.014 0,60 0,60.023 -0.986,61.008 -0.986,73.998 0.015,74.999 ; 0,75.014 0,80.023 ; 0,80 0,80.023 ; 0.015,34.999 -0.986,33.998 -0.986,21.008 0,20.023 0,20 0.015,14.999 -0.986,13.998 -0.986,1.008 0,0.023 0,0 90.013,0 91.915,0.998 98.003,0.998 99.014,2.012 99.014,12.984 98.008,13.998 92.014,13.998 89.98,14.999 90.013,20 91.915,20.998 98.003,20.998 99.014,22.012 99.014,32.984 98.008,33.998 92.014,33.998 89.98,34.999 89.98,39.967 ; 89.98,59.967 89.98,54.999 92.014,53.998 98.008,53.998 99.014,52.984 99.014,42.012 98.003,40.998 91.915,40.998 90.013,40 ; 89.98,79.967 89.98,74.999 92.014,73.998 98.008,73.998 99.014,72.984 99.014,62.012 98.003,60.998 91.915,60.998 90.013,60 ; 90.013,80 91.915,80.998 98.003,80.998 99.014,82.012 99.014,92.984 98.008,93.998 92.014,93.998 89.98,94.999 0.015,94.999 -0.986,93.998 -0.986,81.008 0,80.023 ; 5,20 54.75,20 54.765,14.999 5.015,14.999 5,20 ; 5,40 5.015,34.999 54.765,34.999 54.75,40 5,40 ; 5,60 5.015,54.999 54.765,54.999 54.75,60 5,60 ; 5,80 5.015,74.999 54.765,74.999 54.75,80 5,80 ; 59.75,20 85.013,20 84.979,14.999 59.765,14.999 59.75,20 ; 59.75,40 59.765,34.999 84.979,34.999 85.013,40 59.75,40 ; 59.75,60 59.765,54.999 84.979,54.999 85.013,60 59.75,60 ; 59.75,80 59.765,74.999 84.979,74.999 85.013,80 59.75,80
Mechanical 15:
  lines w0.003: 47.454,4.958 47.505,5.009 ; 47.454,24.958 47.505,25.009 ; 47.454,44.958 47.505,45.009 ; 47.454,64.958 47.505,65.009 ; 47.454,84.958 47.505,85.009 ; 47.615,21.047 47.666,21.098 ; 47.615,41.047 47.666,41.098 ; 47.615,61.047 47.666,61.098 ; 47.615,81.047 47.666,81.098 ; 47.615,101.047 47.666,101.098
